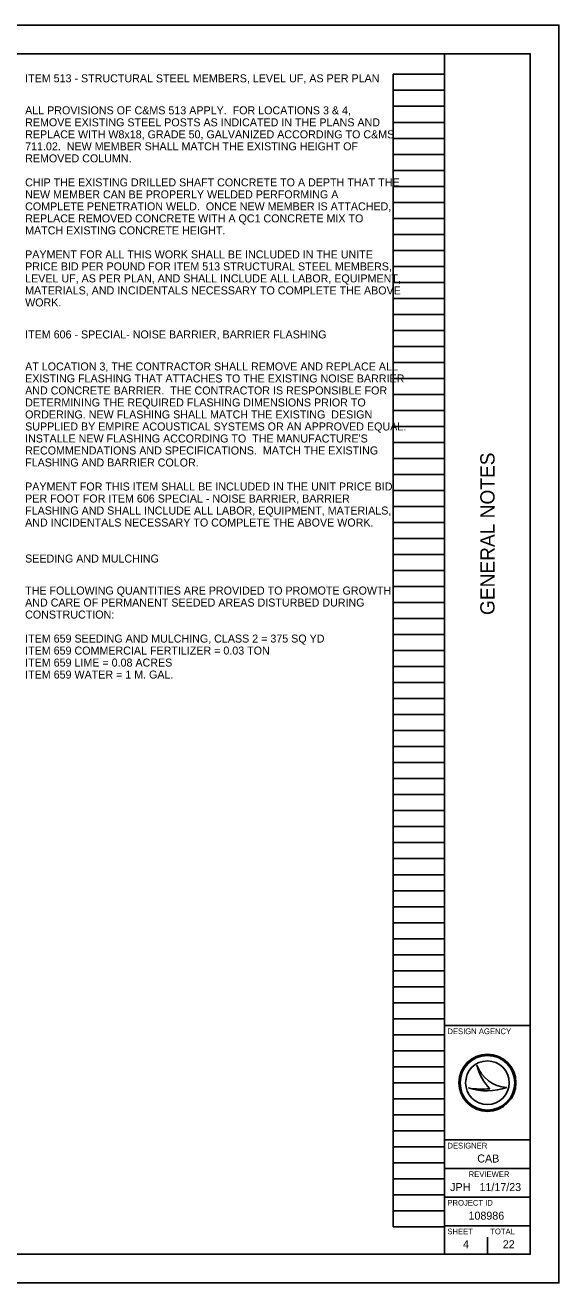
# Model space of a CAD drawing. Extents: x -10.6 to 34, y -3 to 22.
# Drawn here: x 24.66 to 34, y 0 to 22 of the extents above; entities that cross this region are included whole.
import ezdxf

# ---------------------------------------------------------------- set-up
doc = ezdxf.new("R2010")
doc.units = 0
for name, color, linetype in [('SH_Border', 7, 'Continuous'), ('SH_Cut_Line', 7, 'Continuous'), ('SH_Data', 7, 'Continuous'), ('SH_Text', 7, 'Continuous')]:
    doc.layers.add(name, color=color, linetype=linetype)

msp = doc.modelspace()

# ---------------------------------------------------------------- linework, layer by layer
at = {"layer": 'SH_Border'}
for p, q in [((32, 0.5), (32, 21.5)), ((32, 4.5), (33.5, 4.5)), ((32, 2.5), (33.5, 2.5)), ((32, 2), (33.5, 2)), ((32, 1.5), (33.5, 1.5)), ((32, 1), (33.5, 1))]:
    msp.add_line(p, q, dxfattribs=at)
msp.add_lwpolyline([(1.5, 21.5), (33.5, 21.5), (33.5, 0.5), (1.5, 0.5)], close=True, dxfattribs=at)
at = {"layer": 'SH_Cut_Line'}
msp.add_lwpolyline([(0, 0), (34, 0), (34, 22), (0, 22)], close=True, dxfattribs=at)
at = {"layer": 'SH_Data'}
for p, q in [((31.1, 0.98), (31.1, 21.14)), ((31.1, 21.14), (32, 21.14)), ((32, 0.98), (32, 21.14)), ((31.1, 20.86), (32, 20.86)), ((31.1, 20.58), (32, 20.58)), ((31.1, 20.3), (32, 20.3)), ((31.1, 20.02), (32, 20.02)), ((31.1, 19.74), (32, 19.74)), ((31.1, 19.46), (32, 19.46)), ((31.1, 19.18), (32, 19.18)), ((31.1, 18.9), (32, 18.9)), ((31.1, 18.62), (32, 18.62)), ((31.1, 18.34), (32, 18.34)), ((31.1, 18.06), (32, 18.06)), ((31.1, 17.78), (32, 17.78)), ((31.1, 17.5), (32, 17.5)), ((31.1, 17.22), (32, 17.22)), ((31.1, 16.94), (32, 16.94)), ((31.1, 16.66), (32, 16.66)), ((31.1, 16.38), (32, 16.38)), ((31.1, 16.1), (32, 16.1)), ((31.1, 15.82), (32, 15.82)), ((31.1, 15.54), (32, 15.54)), ((31.1, 15.26), (32, 15.26)), ((31.1, 14.98), (32, 14.98)), ((31.1, 14.7), (32, 14.7)), ((31.1, 14.42), (32, 14.42)), ((31.1, 14.14), (32, 14.14)), ((31.1, 13.86), (32, 13.86)), ((31.1, 13.58), (32, 13.58)), ((31.1, 13.3), (32, 13.3)), ((31.1, 13.02), (32, 13.02)), ((31.1, 12.74), (32, 12.74)), ((31.1, 12.46), (32, 12.46)), ((31.1, 12.18), (32, 12.18)), ((31.1, 11.9), (32, 11.9)), ((31.1, 11.62), (32, 11.62)), ((31.1, 11.34), (32, 11.34)), ((31.1, 11.06), (32, 11.06)), ((31.1, 10.78), (32, 10.78)), ((31.1, 10.5), (32, 10.5)), ((31.1, 10.22), (32, 10.22)), ((31.1, 9.94), (32, 9.94)), ((31.1, 9.66), (32, 9.66)), ((31.1, 9.38), (32, 9.38)), ((31.1, 9.1), (32, 9.1)), ((31.1, 8.82), (32, 8.82)), ((31.1, 8.54), (32, 8.54)), ((31.1, 8.26), (32, 8.26)), ((31.1, 7.98), (32, 7.98)), ((31.1, 7.7), (32, 7.7)), ((31.1, 7.42), (32, 7.42)), ((31.1, 7.14), (32, 7.14)), ((31.1, 6.86), (32, 6.86)), ((31.1, 6.58), (32, 6.58)), ((31.1, 6.3), (32, 6.3)), ((31.1, 6.02), (32, 6.02)), ((31.1, 5.74), (32, 5.74)), ((31.1, 5.46), (32, 5.46)), ((31.1, 5.18), (32, 5.18)), ((31.1, 4.9), (32, 4.9)), ((31.1, 4.62), (32, 4.62)), ((31.1, 4.34), (32, 4.34)), ((31.1, 4.06), (32, 4.06)), ((31.1, 3.78), (32, 3.78)), ((32.567, 3.81), (32.567, 3.81)), ((31.1, 3.5), (32, 3.5)), ((32.417, 3.41), (32.417, 3.41)), ((32.75, 3.5), (32.75, 3.5)), ((33.087, 3.419), (33.087, 3.419)), ((31.1, 3.22), (32, 3.22)), ((31.1, 2.94), (32, 2.94)), ((31.1, 2.66), (32, 2.66)), ((31.1, 2.38), (32, 2.38)), ((31.1, 2.1), (32, 2.1)), ((31.1, 1.82), (32, 1.82)), ((31.1, 1.54), (32, 1.54)), ((31.1, 1.26), (32, 1.26)), ((31.1, 0.98), (32, 0.98)), ((32.375, 0.675), (32.375, 0.675)), ((32.75, 0.5), (32.75, 0.8))]:
    msp.add_line(p, q, dxfattribs=at)
for radius in [0.5, 0.477, 0.477, 0.382]:
    msp.add_circle((32.75, 3.5), radius, dxfattribs=at)
for centre, radius, start, end in [((33.116, 3.998), 0.58, 198.9257, 198.9319), ((33.347, 3.97), 0.796, 191.6379, 191.6421), ((33.116, 3.998), 0.58, 198.9319, 267.1657), ((33.347, 3.97), 0.796, 191.6421, 226.0947), ((32.739, 4.37), 1.013, 251.4576, 290.0832), ((32.648, 4.654), 1.266, 259.4964, 259.4995), ((32.739, 4.37), 1.013, 251.4527, 251.4576), ((32.648, 4.654), 1.266, 259.4995, 276.6672)]:
    msp.add_arc(centre, radius, start, end, dxfattribs=at)

# ---------------------------------------------------------------- texts
msp.add_text('GENERAL NOTES', height=0.25, rotation=90, dxfattribs=at).set_placement((32.875, 11.682))
for s, height, p in [('DESIGN AGENCY', 0.1, (32.05, 4.35)), ('DESIGNER', 0.1, (32.05, 2.35)), ('CAB', 0.14, (32.572, 2.105)), ('REVIEWER', 0.1, (32.422, 1.85)), ('JPH', 0.14, (32.098, 1.605)), ('11/17/23', 0.14, (32.611, 1.605)), ('PROJECT ID', 0.1, (32.05, 1.35)), ('108986', 0.14, (32.419, 1.105)), ('SHEET', 0.1, (32.05, 0.85)), ('TOTAL', 0.1, (32.8, 0.85)), ('4', 0.14, (32.322, 0.605)), ('22', 0.14, (33.019, 0.605))]:
    msp.add_text(s, height=height, dxfattribs=at).set_placement(p)
at = {"layer": 'SH_Text'}
for s, p in [('ITEM 513 - STRUCTURAL STEEL MEMBERS, LEVEL UF, AS PER PLAN', (24.66, 21)), ('ALL PROVISIONS OF C&MS 513 APPLY.  FOR LOCATIONS 3 & 4, ', (24.66, 20.44)), ('REMOVE EXISTING STEEL POSTS AS INDICATED IN THE PLANS AND ', (24.66, 20.23)), ('REPLACE WITH W8x18, GRADE 50, GALVANIZED ACCORDING TO C&MS ', (24.66, 20.02)), ('711.02.  NEW MEMBER SHALL MATCH THE EXISTING HEIGHT OF ', (24.66, 19.81)), ('REMOVED COLUMN.', (24.66, 19.6)), ('CHIP THE EXISTING DRILLED SHAFT CONCRETE TO A DEPTH THAT THE ', (24.66, 19.18)), ('NEW MEMBER CAN BE PROPERLY WELDED PERFORMING A ', (24.66, 18.97)), ('COMPLETE PENETRATION WELD.  ONCE NEW MEMBER IS ATTACHED, ', (24.66, 18.76)), ('REPLACE REMOVED CONCRETE WITH A QC1 CONCRETE MIX TO ', (24.66, 18.55)), ('MATCH EXISTING CONCRETE HEIGHT.', (24.66, 18.34)), ('PAYMENT FOR ALL THIS WORK SHALL BE INCLUDED IN THE UNITE ', (24.66, 17.92)), ('PRICE BID PER POUND FOR ITEM 513 STRUCTURAL STEEL MEMBERS, ', (24.66, 17.71)), ('LEVEL UF, AS PER PLAN, AND SHALL INCLUDE ALL LABOR, EQUIPMENT, ', (24.66, 17.5)), ('MATERIALS, AND INCIDENTALS NECESSARY TO COMPLETE THE ABOVE ', (24.66, 17.29)), ('WORK.', (24.66, 17.08)), ('ITEM 606 - SPECIAL- NOISE BARRIER, BARRIER FLASHING', (24.66, 16.52)), ('AT LOCATION 3, THE CONTRACTOR SHALL REMOVE AND REPLACE ALL ', (24.66, 15.96)), ('EXISTING FLASHING THAT ATTACHES TO THE EXISTING NOISE BARRIER ', (24.66, 15.75)), ('AND CONCRETE BARRIER.  THE CONTRACTOR IS RESPONSIBLE FOR ', (24.66, 15.54)), ('DETERMINING THE REQUIRED FLASHING DIMENSIONS PRIOR TO ', (24.66, 15.33)), ('ORDERING. NEW FLASHING SHALL MATCH THE EXISTING  DESIGN ', (24.66, 15.12)), ('SUPPLIED BY EMPIRE ACOUSTICAL SYSTEMS OR AN APPROVED EQUAL. ', (24.66, 14.91)), ("INSTALLE NEW FLASHING ACCORDING TO  THE MANUFACTURE'S ", (24.66, 14.7)), ('RECOMMENDATIONS AND SPECIFICATIONS.  MATCH THE EXISTING ', (24.66, 14.49)), ('FLASHING AND BARRIER COLOR.', (24.66, 14.28)), ('PAYMENT FOR THIS ITEM SHALL BE INCLUDED IN THE UNIT PRICE BID ', (24.66, 13.86)), ('PER FOOT FOR ITEM 606 SPECIAL - NOISE BARRIER, BARRIER ', (24.66, 13.65)), ('FLASHING AND SHALL INCLUDE ALL LABOR, EQUIPMENT, MATERIALS, ', (24.66, 13.44)), ('AND INCIDENTALS NECESSARY TO COMPLETE THE ABOVE WORK. ', (24.66, 13.23)), ('SEEDING AND MULCHING', (24.66, 12.6)), ('THE FOLLOWING QUANTITIES ARE PROVIDED TO PROMOTE GROWTH ', (24.66, 12.04)), ('AND CARE OF PERMANENT SEEDED AREAS DISTURBED DURING ', (24.66, 11.83)), ('CONSTRUCTION:', (24.66, 11.62)), ('ITEM 659 SEEDING AND MULCHING, CLASS 2 = 375 SQ YD', (24.66, 11.2)), ('ITEM 659 COMMERCIAL FERTILIZER = 0.03 TON', (24.66, 10.99)), ('ITEM 659 LIME = 0.08 ACRES', (24.66, 10.78)), ('ITEM 659 WATER = 1 M. GAL.', (24.66, 10.57))]:
    msp.add_text(s, height=0.14, dxfattribs=at).set_placement(p)

doc.saveas('drawing.dxf')
